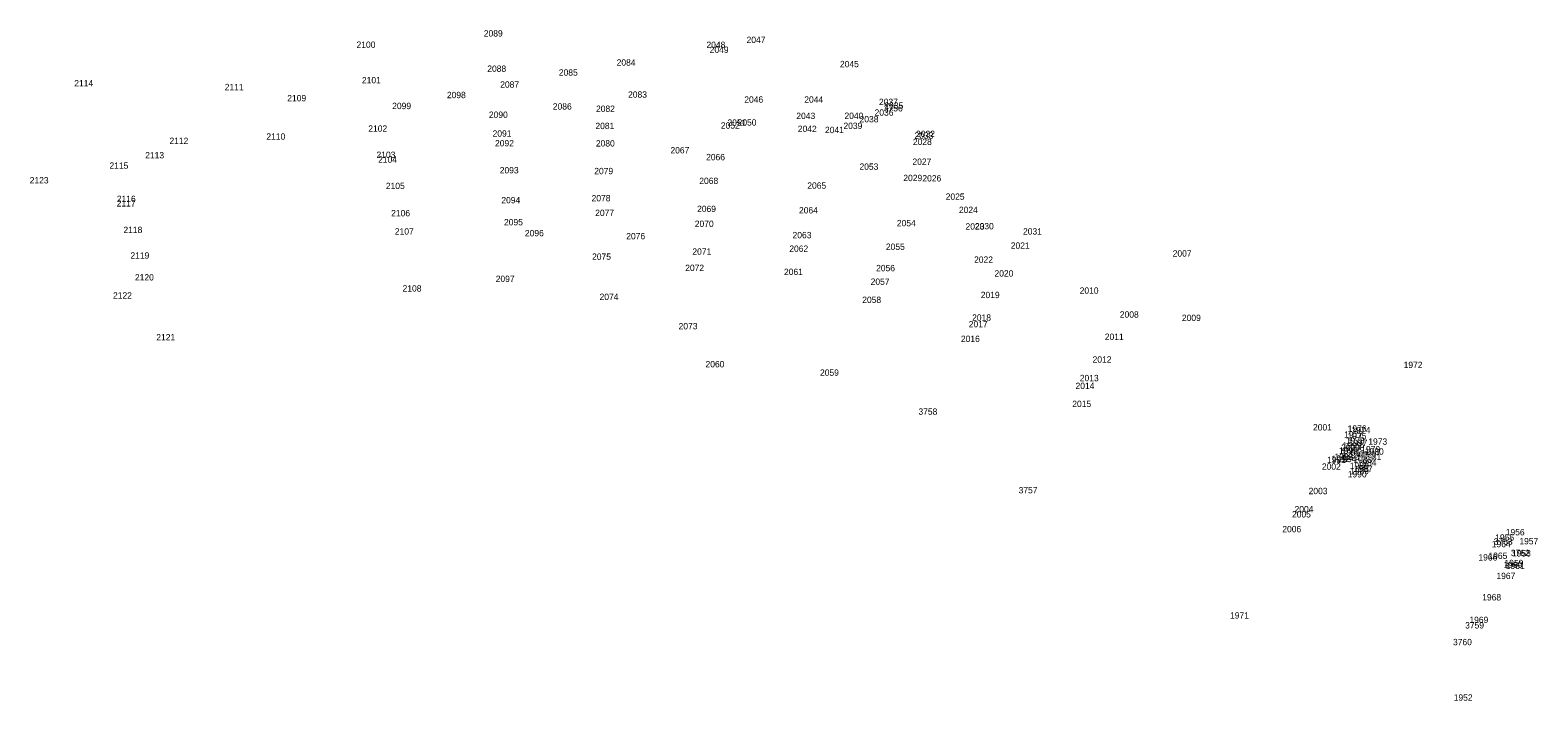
# Model space of a CAD drawing. Extents: x -740053 to -737517, y -1033516 to -1032465.
# Drawn here: x -738412.3 to -738281.6, y -1032546.5 to -1032488.4 of the extents above; entities that cross this region are included whole.
import ezdxf

# ---------------------------------------------------------------- set-up
doc = ezdxf.new("R2010")
doc.units = 0
doc.layers.add('bod-cislo', color=7, linetype='Continuous')

msp = doc.modelspace()

# ---------------------------------------------------------------- texts
at = {"layer": 'bod-cislo'}
for s, p in [('2100', (-738383.98, -1032489.93)), ('2089', (-738372.95, -1032488.95)), ('2048', (-738353.66, -1032489.94)), ('2047', (-738350.18, -1032489.51)), ('2049', (-738353.38, -1032490.37)), ('2088', (-738372.65, -1032492.01)), ('2085', (-738366.45, -1032492.34)), ('2084', (-738361.44, -1032491.47)), ('2045', (-738342.09, -1032491.61)), ('2114', (-738408.44, -1032493.27)), ('2111', (-738395.4, -1032493.6)), ('2101', (-738383.51, -1032493)), ('2087', (-738371.53, -1032493.38)), ('2109', (-738389.98, -1032494.56)), ('2099', (-738380.89, -1032495.24)), ('2098', (-738376.15, -1032494.29)), ('2083', (-738360.45, -1032494.25)), ('2046', (-738350.38, -1032494.68)), ('2044', (-738345.18, -1032494.68)), ('2037', (-738338.71, -1032494.89)), ('2035', (-738338.24, -1032495.21)), ('2090', (-738372.51, -1032496)), ('2086', (-738366.97, -1032495.28)), ('2082', (-738363.23, -1032495.48)), ('2043', (-738345.87, -1032496.1)), ('2040', (-738341.7, -1032496.09)), ('2038', (-738340.39, -1032496.39)), ('2036', (-738339.09, -1032495.81)), ('3756', (-738338.29, -1032495.44)), ('2102', (-738382.96, -1032497.2)), ('2091', (-738372.19, -1032497.63)), ('2081', (-738363.28, -1032496.97)), ('2052', (-738352.41, -1032496.93)), ('2051', (-738351.84, -1032496.68)), ('2050', (-738350.96, -1032496.67)), ('2042', (-738345.74, -1032497.22)), ('2041', (-738343.39, -1032497.32)), ('2039', (-738341.79, -1032496.96)), ('2033', (-738335.63, -1032497.8)), ('2032', (-738335.5, -1032497.66)), ('2112', (-738400.19, -1032498.26)), ('2110', (-738391.79, -1032497.89)), ('2092', (-738371.98, -1032498.47)), ('2080', (-738363.24, -1032498.48)), ('2067', (-738356.78, -1032499.08)), ('2028', (-738335.77, -1032498.35)), ('2115', (-738405.39, -1032500.41)), ('2113', (-738402.29, -1032499.51)), ('2103', (-738382.25, -1032499.47)), ('2104', (-738382.11, -1032499.88)), ('2066', (-738353.69, -1032499.67)), ('2027', (-738335.81, -1032500.07)), ('2123', (-738412.3, -1032501.68)), ('2093', (-738371.57, -1032500.81)), ('2079', (-738363.38, -1032500.88)), ('2068', (-738354.28, -1032501.73)), ('2053', (-738340.4, -1032500.5)), ('2029', (-738336.6, -1032501.48)), ('2026', (-738334.95, -1032501.51)), ('2105', (-738381.44, -1032502.17)), ('2065', (-738344.92, -1032502.14)), ('2025', (-738332.93, -1032503.1)), ('2117', (-738404.76, -1032503.68)), ('2116', (-738404.75, -1032503.29)), ('2094', (-738371.43, -1032503.4)), ('2078', (-738363.61, -1032503.23)), ('2069', (-738354.47, -1032504.16)), ('2064', (-738345.64, -1032504.28)), ('2024', (-738331.78, -1032504.24)), ('2106', (-738380.98, -1032504.53)), ('2095', (-738371.2, -1032505.31)), ('2077', (-738363.3, -1032504.5)), ('2070', (-738354.67, -1032505.45)), ('2054', (-738337.16, -1032505.39)), ('2023', (-738331.21, -1032505.68)), ('2030', (-738330.4, -1032505.66)), ('2118', (-738404.18, -1032505.98)), ('2107', (-738380.66, -1032506.11)), ('2096', (-738369.39, -1032506.26)), ('2076', (-738360.61, -1032506.52)), ('2063', (-738346.2, -1032506.43)), ('2031', (-738326.23, -1032506.11)), ('2119', (-738403.57, -1032508.2)), ('2075', (-738363.57, -1032508.3)), ('2071', (-738354.88, -1032507.86)), ('2062', (-738346.48, -1032507.61)), ('2055', (-738338.11, -1032507.44)), ('2021', (-738327.29, -1032507.34)), ('2007', (-738313.26, -1032508.02)), ('2072', (-738355.5, -1032509.27)), ('2061', (-738346.94, -1032509.62)), ('2056', (-738338.96, -1032509.29)), ('2022', (-738330.47, -1032508.56)), ('2120', (-738403.18, -1032510.09)), ('2097', (-738371.92, -1032510.22)), ('2057', (-738339.43, -1032510.47)), ('2020', (-738328.7, -1032509.75)), ('2122', (-738405.08, -1032511.66)), ('2108', (-738379.99, -1032511.05)), ('2074', (-738362.92, -1032511.78)), ('2058', (-738340.16, -1032512.04)), ('2019', (-738329.89, -1032511.62)), ('2010', (-738321.32, -1032511.24)), ('2008', (-738317.84, -1032513.31)), ('2073', (-738356.07, -1032514.32)), ('2017', (-738330.93, -1032514.15)), ('2018', (-738330.64, -1032513.58)), ('2009', (-738312.46, -1032513.6)), ('2121', (-738401.33, -1032515.28)), ('2016', (-738331.61, -1032515.42)), ('2011', (-738319.14, -1032515.24)), ('2012', (-738320.2, -1032517.21)), ('2060', (-738353.74, -1032517.62)), ('2059', (-738343.82, -1032518.35)), ('1972', (-738293.25, -1032517.68)), ('2014', (-738321.68, -1032519.5)), ('2013', (-738321.31, -1032518.82)), ('2015', (-738321.96, -1032521.06)), ('3758', (-738335.29, -1032521.73)), ('2001', (-738301.1, -1032523.09)), ('1977', (-738298.4, -1032523.72)), ('1975', (-738298.11, -1032523.85)), ('1976', (-738298.1, -1032523.2)), ('1974', (-738297.76, -1032523.33)), ('1996', (-738298.85, -1032525.1)), ('2000', (-738298.67, -1032524.85)), ('1995', (-738298.62, -1032525.26)), ('1999', (-738298.54, -1032524.66)), ('1998', (-738298.28, -1032524.84)), ('1978', (-738298.26, -1032524.23)), ('1997', (-738298.03, -1032524.44)), ('1979', (-738296.92, -1032524.99)), ('1980', (-738296.61, -1032525.19)), ('1973', (-738296.31, -1032524.33)), ('2002', (-738300.33, -1032526.49)), ('1991', (-738299.88, -1032525.92)), ('1992', (-738299.5, -1032525.81)), ('1993', (-738299.24, -1032525.65)), ('1994', (-738298.97, -1032525.84)), ('1988', (-738297.99, -1032525.46)), ('1986', (-738297.91, -1032526.42)), ('1985', (-738297.59, -1032525.9)), ('1983', (-738297.4, -1032525.66)), ('1984', (-738297.24, -1032526.15)), ('1982', (-738297.24, -1032525.48)), ('1981', (-738296.82, -1032525.66)), ('1990', (-738298.09, -1032527.16)), ('1989', (-738297.89, -1032526.88)), ('1987', (-738297.57, -1032526.69)), ('3757', (-738326.61, -1032528.54)), ('2003', (-738301.48, -1032528.61)), ('2004', (-738302.7, -1032530.18)), ('2005', (-738302.92, -1032530.63)), ('2006', (-738303.76, -1032531.91)), ('3763', (-738285.44, -1032532.99)), ('1955', (-738285.31, -1032532.64)), ('1956', (-738284.4, -1032532.18)), ('1957', (-738283.22, -1032532.96)), ('1966', (-738286.77, -1032534.36)), ('1965', (-738285.9, -1032534.22)), ('1964', (-738285.61, -1032533.21)), ('3762', (-738283.96, -1032533.98)), ('1958', (-738283.86, -1032534.01)), ('1960', (-738284.59, -1032535.01)), ('1959', (-738284.51, -1032534.85)), ('1961', (-738284.4, -1032535.1)), ('1967', (-738285.21, -1032535.97)), ('1968', (-738286.44, -1032537.82)), ('1971', (-738308.29, -1032539.39)), ('3759', (-738287.92, -1032540.25)), ('1969', (-738287.55, -1032539.78)), ('3760', (-738288.97, -1032541.7)), ('1952', (-738288.91, -1032546.51))]:
    msp.add_text(s, height=0.55, dxfattribs=at).set_placement(p)

doc.saveas('drawing.dxf')
